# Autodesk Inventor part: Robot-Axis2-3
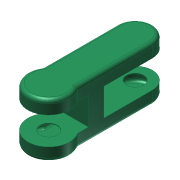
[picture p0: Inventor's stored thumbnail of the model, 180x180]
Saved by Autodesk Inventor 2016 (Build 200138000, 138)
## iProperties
Shininess: 21.0
Length Units: 11269
Angle Units: 11279
Time Units: 11290
Mass Units: 11283
Length Display Precision: 3
Angle Display Precision: 2
Created: 2001-08
Part Number: Robot-Axis2-3
Document SubType Name: ﾓﾃﾞﾘﾝｸﾞ
Designer: Administrator
Density: 1 g/cm^3
Material: Generic
Mass: 395.434 g
Surface Area: 3966.98 cm^2
Volume: 395.434 cm^3
Appearance: Sea Green
Density: 0.0
Volumn: 0.0
Area: 0.0
PropertySet Name: Model Information
Control State: 0
Master: False
Checked Out: False
Author: Administrator
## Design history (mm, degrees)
node "作業平面1"
sketch "ｽｹｯﾁ2"
  geometry: L1 (0, 0)-(0, 250); L2 (0, 250)-(-50, 250); L3 (-50, 250)-(-50, 33.166); L4 (0, 250)-(50, 250); L5 (50, 250)-(50, 33.166); A1 r 60 centre (0, 0) between (-50, 33.166) and (50, 33.166); A2 r 50 centre (0, 250) between (-50, 250) and (50, 250)
  constraints: 10 end point, 4 point on circle, 2 centre point, 2 perpendicular, 2 tangent, 1 coincident, 1 vertical, 1 other
  dimensions: "d1" = 120 diameter of A1; "d2" = 250 distance of L1.start L1.end; "d3" = 100 diameter of A2
extrude "押し出し1" new body sketch "ｽｹｯﾁ2" distance "d4" = 38; taper "d5" = 0 deg
sketch "ｽｹｯﾁ3"
  geometry: L1 (-50, 250)-(-50, 33.166) reference; L2 (50, 33.166)-(50, 250) reference; L3 (-50, 65)-(50, 65); L4 (50, 65)-(50, 110); L5 (50, 110)-(-50, 110); L6 (-50, 110)-(-50, 65); C1 r 60 at (0, 0); A1 r 60 centre (0, 0) between (-50, 33.166) and (50, 33.166) reference
  constraints: 8 end point, 2 parallel, 2 point on line, 1 centre point, 1 coincident, 1 concentric, 1 horizontal, 1 perpendicular
  dimensions: "d7" = 65 distance from line of L3 C1.centre; "d8" = 140 distance from line of L5 L1.start
extrude "押し出し2" join sketch "ｽｹｯﾁ3" stored distance "d9" = 10; taper "d10" = 0 deg
shell "Shell1" dims "d11" = 2
sketch "Sketch4"
  geometry: A1 r 60 centre (0, 0) between (-50, 33.166) and (50, 33.166) reference
hole "Hole1" sketch "Sketch4" at (0, 0) diameter "d12" = 50; stored, may be unused: countersink angle "d16" = 82 deg, drill point angle "d18" = 118 deg; dims "d13" = 6, "d14" = 4, "d15" = 2, "d17" = 2
sketch "Sketch5"
  geometry: A1 r 60 centre (0, 0) between (-50, 33.166) and (50, 33.166) reference
hole "Hole2" sketch "Sketch5" at (0, 0) diameter "d19" = 50; stored, may be unused: countersink angle "d23" = 82 deg, drill point angle "d25" = 118 deg; dims "d20" = 6, "d21" = 4, "d22" = 2, "d24" = 2
sketch "Sketch6"
  geometry: A1 r 50 centre (0, 250) between (50, 250) and (-50, 250) reference
hole "Hole3" sketch "Sketch6" at (0, 250) diameter "d26" = 50; stored, may be unused: countersink angle "d30" = 82 deg, drill point angle "d32" = 118 deg; dims "d27" = 6, "d28" = 4, "d29" = 2, "d31" = 2
sketch "Sketch7"
  geometry: A1 r 50 centre (0, 0) between (50, 0) and (-50, 0) reference
hole "Hole4" sketch "Sketch7" at (0, 0) diameter "d33" = 50; stored, may be unused: countersink angle "d37" = 82 deg, drill point angle "d39" = 118 deg; dims "d34" = 6, "d35" = 4, "d36" = 2, "d38" = 2
body "Solid1"
fillet "Fillet" dims "d6" = 10
mirror "Mirror"
